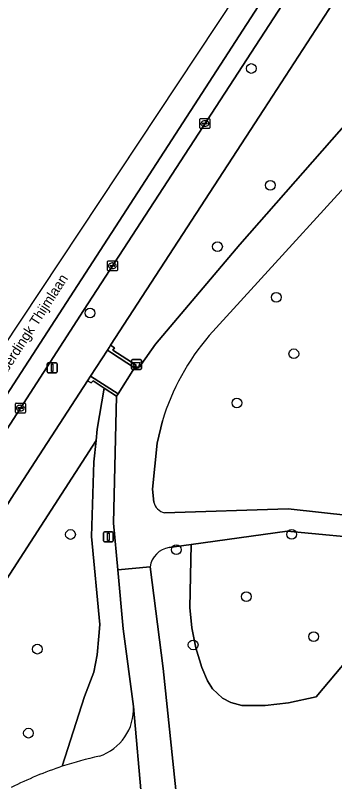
# Model space of a CAD drawing. Extents: x 161402 to 161933, y 381647 to 382315.
# Drawn here: x 161500.4 to 161532.4, y 381932.5 to 382009.5 of the extents above; entities that cross this region are included whole.
import ezdxf

# ---------------------------------------------------------------- set-up
doc = ezdxf.new("R2010")
doc.units = 0
for name, color, linetype in [('IMGEO_Afvalbak', 7, 'Continuous'), ('IMGEO_Boom', 7, 'Continuous'), ('IMGEO_Groenvoorziening', 7, 'Continuous'), ('IMGEO_Kolk', 7, 'Continuous'), ('IMGEO_Lichtmast', 7, 'Continuous'), ('IMGEO_Muur', 7, 'Continuous'), ('IMGEO_Openbare_ruimte_label', 7, 'Continuous'), ('IMGEO_Rijbaan_lokaal_gesloten', 7, 'Continuous'), ('IMGEO_Rijbaan_lokaal_open', 7, 'Continuous'), ('IMGEO_Voetpad_gesloten', 7, 'Continuous'), ('IMGEO_Voetpad_op_trap', 7, 'Continuous'), ('IMGEO_Voetpad_open', 7, 'Continuous')]:
    doc.layers.add(name, color=color, linetype=linetype)

msp = doc.modelspace()

# ---------------------------------------------------------------- linework, layer by layer
at = {"layer": 'IMGEO_Afvalbak'}
for p, q in [((161512.056, 381973.98), (161512.056, 381974.78)), ((161512.056, 381974.78), (161512.056, 381973.98)), ((161512.156, 381974.88), (161512.946, 381974.88)), ((161512.946, 381974.88), (161512.156, 381974.88)), ((161513.046, 381974.78), (161513.046, 381973.98)), ((161513.046, 381973.98), (161513.046, 381974.78)), ((161512.946, 381973.88), (161512.156, 381973.88)), ((161512.156, 381973.88), (161512.946, 381973.88))]:
    msp.add_line(p, q, dxfattribs=at)
msp.add_lwpolyline([(161512.199, 381974.594), (161512.903, 381974.594), (161512.754, 381974.124), (161512.348, 381974.124), (161512.199, 381974.594)], dxfattribs=at)
for centre, start, end in [((161512.156, 381974.78), 90, 180), ((161512.156, 381974.78), 90, 180), ((161512.946, 381974.78), 0, 90), ((161512.946, 381974.78), 360, 90), ((161512.156, 381973.98), 180, 270), ((161512.156, 381973.98), 180, 270), ((161512.946, 381973.98), 270, 0), ((161512.946, 381973.98), 270, 0)]:
    msp.add_arc(centre, 0.1, start, end, dxfattribs=at)
at = {"layer": 'IMGEO_Boom'}
for centre in [(161524.069, 382004.122), (161525.982, 381992.389), (161520.681, 381986.224), (161526.576, 381981.129), (161507.896, 381979.545), (161528.346, 381975.453), (161522.628, 381970.508), (161505.933, 381957.295), (161528.12, 381957.302), (161516.555, 381955.763), (161523.568, 381951.047), (161530.341, 381947.03), (161502.618, 381945.772), (161518.24, 381946.2), (161501.719, 381937.331)]:
    msp.add_circle(centre, 0.489, dxfattribs=at)
at = {"layer": 'IMGEO_Groenvoorziening'}
for points in [[(161550.139, 382016.903), (161566.397, 382035.429), (161561.912, 382038.8), (161560.125, 382041.115), (161560.053, 382046.091), (161561.918, 382049.386), (161564.736, 382052.445), (161569.199, 382053.861), (161571.62, 382051.637), (161574.693, 382046.208), (161579.356, 382052.267), (161579.545, 382052.829), (161579.122, 382053.921), (161568.086, 382063.783), (161567.337, 382064.038), (161566.628, 382063.688), (161525.324, 382000), (161509.956, 381976.304), (161510.352, 381976.047), (161510.195, 381975.805), (161512.522, 381974.297), (161512.354, 381974.043)], [(161513.027, 381974.379), (161514.478, 381976.419), (161522.917, 381986.45), (161534.836, 382000), (161550.139, 382016.903)], [(161544.568, 381990.984), (161544.697, 381994.341), (161539.026, 381998.34), (161519.862, 381977.295)], [(161515.352, 381959.463), (161527.77, 381959.887), (161537.2, 381958.819), (161538.012, 381964.131), (161537.399, 381965.184), (161541.408, 381970.096), (161542.413, 381969.37), (161547.271, 381970.949), (161546.429, 381973.583)], [(161510.676, 381953.741), (161510.253, 381958.443), (161510.563, 381971.196), (161509.308, 381972.015), (161508.618, 381967.87), (161508.501, 381966.732), (161508.281, 381964.587), (161508.029, 381957.094), (161508.87, 381948.254), (161508.777, 381947.074), (161508.622, 381945.207), (161508.281, 381943.455), (161507.356, 381941.013), (161505.105, 381933.996)], [(161515.15, 381968.709), (161514.646, 381966.471), (161514.174, 381961.84), (161514.294, 381960.547)], [(161505.105, 381933.996), (161507.356, 381941.013), (161508.281, 381943.455), (161508.622, 381945.207), (161508.777, 381947.074), (161508.87, 381948.254), (161508.029, 381957.094), (161508.281, 381964.587), (161508.501, 381966.732), (161469.767, 381906.69), (161463.799, 381897.019), (161472.803, 381891.338), (161466.75, 381881.87), (161480.283, 381895.461)], [(161533.668, 381906.095), (161532.917, 381915.131), (161532.824, 381921.008), (161533.225, 381929.262), (161534.202, 381939.899), (161534.991, 381946.237), (161530.572, 381940.988), (161527.811, 381940.367), (161525.479, 381940.12), (161523.133, 381940.118), (161522.019, 381940.405), (161521.193, 381940.842), (161520.168, 381941.793), (161519.671, 381942.584), (161519.118, 381943.929), (161518.506, 381945.898), (161518.104, 381947.92), (161517.916, 381949.973), (161518.029, 381956.285), (161515.84, 381955.982)], [(161512.254, 381940.023), (161511.211, 381947.806), (161510.676, 381953.741)], [(161513.937, 381954.035), (161515.234, 381943.813), (161516.591, 381930.663)]]:
    msp.add_lwpolyline(points, dxfattribs=at)
for points in [[(161463.799, 381897.019), (161469.767, 381906.69), (161508.501, 381966.732), (161508.618, 381967.87), (161509.308, 381972.015), (161508.198, 381972.739), (161508.017, 381972.531), (161507.649, 381972.745), (161500, 381960.897), (161499.565, 381960.223), (161466.384, 381908.825), (161460.416, 381899.153)], [(161535.316, 381948.041), (161535.492, 381949.019), (161536.744, 381955.964), (161536.884, 381956.742), (161527.675, 381957.619), (161518.029, 381956.285), (161517.916, 381949.973), (161518.104, 381947.92), (161518.506, 381945.898), (161519.118, 381943.929), (161519.671, 381942.584), (161520.168, 381941.793), (161521.193, 381940.842), (161522.019, 381940.405), (161523.133, 381940.118), (161525.479, 381940.12), (161527.811, 381940.367), (161530.572, 381940.988), (161534.991, 381946.237)]]:
    msp.add_lwpolyline(points, close=True, dxfattribs=at)
for centre, radius, start, end in [((161538.145, 381961.675), 24.046, 139.49162, 162.99238), ((161512.522, 381974.549), 0.533, 251.63031, 341.43166), ((161515.722, 381960.882), 1.466, 193.20622, 255.40291), ((161516.156, 381953.77), 2.235, 98.12568, 173.18388), ((161507.248, 381939.774), 5.012, 288.4124, 2.8499), ((161516.698, 381899.034), 36.834, 102.33201, 108.34471), ((161516.832, 381898.676), 37.216, 108.36728, 116.88998)]:
    msp.add_arc(centre, radius, start, end, dxfattribs=at)
at = {"layer": 'IMGEO_Kolk'}
for p, q in [((161518.916, 381998.165), (161518.916, 381999.017)), ((161518.991, 381999.091), (161519.843, 381999.091)), ((161519.175, 381998.585), (161519.175, 381998.597)), ((161519.613, 381998.548), (161519.215, 381998.548)), ((161519.218, 381998.634), (161519.616, 381998.634)), ((161519.404, 381998.871), (161519.429, 381998.871)), ((161519.659, 381998.597), (161519.659, 381998.585)), ((161519.917, 381999.017), (161519.917, 381998.165)), ((161519.843, 381998.091), (161518.991, 381998.091)), ((161519.427, 381998.311), (161519.402, 381998.311)), ((161509.644, 381983.873), (161509.644, 381984.725)), ((161509.719, 381984.799), (161510.571, 381984.799)), ((161510.132, 381984.579), (161510.157, 381984.579)), ((161510.645, 381984.725), (161510.645, 381983.873)), ((161510.571, 381983.799), (161509.719, 381983.799)), ((161509.903, 381984.293), (161509.903, 381984.305)), ((161510.341, 381984.256), (161509.943, 381984.256)), ((161509.946, 381984.342), (161510.344, 381984.342)), ((161510.155, 381984.019), (161510.13, 381984.019)), ((161510.387, 381984.305), (161510.387, 381984.293)), ((161500.415, 381969.577), (161500.415, 381970.429)), ((161500.49, 381970.503), (161501.342, 381970.503)), ((161500.674, 381969.997), (161500.674, 381970.009)), ((161501.112, 381969.96), (161500.714, 381969.96)), ((161500.717, 381970.046), (161501.115, 381970.046)), ((161500.903, 381970.283), (161500.928, 381970.283)), ((161501.158, 381970.009), (161501.158, 381969.997)), ((161501.416, 381970.429), (161501.416, 381969.577)), ((161501.342, 381969.503), (161500.49, 381969.503)), ((161500.926, 381969.723), (161500.901, 381969.723))]:
    msp.add_line(p, q, dxfattribs=at)
for points in [[(161518.916, 381998.165), (161518.916, 381999.017)], [(161518.991, 381999.091), (161519.843, 381999.091)], [(161519.917, 381999.017), (161519.917, 381998.165)], [(161519.843, 381998.091), (161518.991, 381998.091)], [(161509.644, 381983.873), (161509.644, 381984.725)], [(161509.719, 381984.799), (161510.571, 381984.799)], [(161510.645, 381984.725), (161510.645, 381983.873)], [(161510.571, 381983.799), (161509.719, 381983.799)], [(161500.415, 381969.577), (161500.415, 381970.429)], [(161500.49, 381970.503), (161501.342, 381970.503)], [(161501.416, 381970.429), (161501.416, 381969.577)], [(161501.342, 381969.503), (161500.49, 381969.503)]]:
    msp.add_lwpolyline(points, dxfattribs=at)
for centre, radius, start, end in [((161518.993, 381999.015), 0.0765, 91.55205, 178.44795), ((161518.993, 381999.015), 0.0765, 91.55205, 178.44795), ((161519.215, 381998.594), 0.0403, 85.87752, 175.75265), ((161519.212, 381998.584), 0.0366, 178.93798, 274.71019), ((161519.616, 381998.591), 0.043, 264.86636, 352.45326), ((161519.62, 381998.596), 0.0386, 1.73085, 96.63898), ((161519.841, 381999.015), 0.0765, 1.55205, 88.44795), ((161519.841, 381999.015), 0.0765, 1.55205, 88.44795), ((161518.993, 381998.167), 0.0765, 181.55205, 268.44795), ((161518.993, 381998.167), 0.0765, 181.55205, 268.44795), ((161519.841, 381998.167), 0.0765, 271.55205, 358.44795), ((161519.841, 381998.167), 0.0765, 271.55205, 358.44795), ((161509.721, 381984.723), 0.0765, 91.55205, 178.44795), ((161509.721, 381984.723), 0.0765, 91.55205, 178.44795), ((161510.569, 381984.723), 0.0765, 1.55205, 88.44795), ((161510.569, 381984.723), 0.0765, 1.55205, 88.44795), ((161509.721, 381983.875), 0.0765, 181.55205, 268.44795), ((161509.721, 381983.875), 0.0765, 181.55205, 268.44795), ((161509.943, 381984.302), 0.0403, 85.87752, 175.75265), ((161509.94, 381984.292), 0.0366, 178.93798, 274.71019), ((161510.344, 381984.299), 0.043, 264.86636, 352.45326), ((161510.348, 381984.304), 0.0386, 1.73085, 96.63898), ((161510.569, 381983.875), 0.0765, 271.55205, 358.44795), ((161510.569, 381983.875), 0.0765, 271.55205, 358.44795), ((161500.492, 381970.427), 0.0765, 91.55205, 178.44795), ((161500.492, 381970.427), 0.0765, 91.55205, 178.44795), ((161500.714, 381970.006), 0.0403, 85.87752, 175.75265), ((161500.711, 381969.996), 0.0366, 178.93798, 274.71019), ((161501.115, 381970.003), 0.043, 264.86636, 352.45326), ((161501.119, 381970.008), 0.0386, 1.73085, 96.63898), ((161501.34, 381970.427), 0.0765, 1.55205, 88.44795), ((161501.34, 381970.427), 0.0765, 1.55205, 88.44795), ((161500.492, 381969.579), 0.0765, 181.55205, 268.44795), ((161500.492, 381969.579), 0.0765, 181.55205, 268.44795), ((161501.34, 381969.579), 0.0765, 271.55205, 358.44795), ((161501.34, 381969.579), 0.0765, 271.55205, 358.44795)]:
    msp.add_arc(centre, radius, start, end, dxfattribs=at)
for centre, major_axis, ratio, start_param, end_param in [((161519.403, 381998.591), (-0.387, 0.002), 0.722429, 4.712389, 7.853982), ((161519.428, 381998.591), (-0.39, 0.002), 0.717154, 1.570796, 4.712389), ((161510.131, 381984.299), (-0.387, 0.002), 0.722429, 4.712389, 7.853982), ((161510.156, 381984.299), (-0.39, 0.002), 0.717154, 1.570796, 4.712389), ((161500.902, 381970.003), (-0.387, 0.002), 0.722429, 4.712389, 7.853982), ((161500.927, 381970.003), (-0.39, 0.002), 0.717154, 1.570796, 4.712389)]:
    msp.add_ellipse(centre, major_axis=major_axis, ratio=ratio, start_param=start_param, end_param=end_param, dxfattribs=at)
at = {"layer": 'IMGEO_Lichtmast'}
for p, q in [((161503.696, 381974.552), (161504.486, 381974.552)), ((161504.486, 381974.552), (161503.696, 381974.552)), ((161503.596, 381973.652), (161503.596, 381974.452)), ((161503.596, 381974.452), (161503.596, 381973.652)), ((161504.586, 381974.452), (161504.586, 381973.652)), ((161504.586, 381973.652), (161504.586, 381974.452)), ((161504.486, 381973.552), (161503.696, 381973.552)), ((161503.696, 381973.552), (161504.486, 381973.552)), ((161509.235, 381956.65), (161509.235, 381957.45)), ((161509.235, 381957.45), (161509.235, 381956.65)), ((161509.335, 381957.55), (161510.125, 381957.55)), ((161510.125, 381957.55), (161509.335, 381957.55)), ((161510.225, 381957.45), (161510.225, 381956.65)), ((161510.225, 381956.65), (161510.225, 381957.45)), ((161510.125, 381956.55), (161509.335, 381956.55)), ((161509.335, 381956.55), (161510.125, 381956.55))]:
    msp.add_line(p, q, dxfattribs=at)
for points in [[(161504.016, 381974.427), (161504.166, 381974.427), (161504.166, 381973.677), (161504.016, 381973.677), (161504.016, 381974.427)], [(161509.655, 381957.425), (161509.805, 381957.425), (161509.805, 381956.675), (161509.655, 381956.675), (161509.655, 381957.425)]]:
    msp.add_lwpolyline(points, dxfattribs=at)
for centre, start, end in [((161503.696, 381974.452), 90, 180), ((161503.696, 381974.452), 90, 180), ((161504.486, 381974.452), 0, 90), ((161504.486, 381974.452), 360, 90), ((161503.696, 381973.652), 180, 270), ((161503.696, 381973.652), 180, 270), ((161504.486, 381973.652), 270, 0), ((161504.486, 381973.652), 270, 0), ((161509.335, 381957.45), 90, 180), ((161509.335, 381957.45), 90, 180), ((161510.125, 381957.45), 0, 90), ((161510.125, 381957.45), 360, 90), ((161509.335, 381956.65), 180, 270), ((161509.335, 381956.65), 180, 270), ((161510.125, 381956.65), 270, 0), ((161510.125, 381956.65), 270, 0)]:
    msp.add_arc(centre, 0.1, start, end, dxfattribs=at)
at = {"layer": 'IMGEO_Muur'}
for points in [[(161510.195, 381975.805), (161510.352, 381976.047), (161509.956, 381976.304), (161509.806, 381976.073), (161509.648, 381975.83), (161510.055, 381975.566), (161512.354, 381974.043), (161512.522, 381974.297)], [(161507.953, 381973.214), (161507.649, 381972.745), (161508.017, 381972.531), (161508.198, 381972.739), (161509.308, 381972.015), (161510.563, 381971.196), (161510.709, 381971.428)]]:
    msp.add_lwpolyline(points, close=True, dxfattribs=at)
at = {"layer": 'IMGEO_Rijbaan_lokaal_gesloten'}
msp.add_lwpolyline([(161507.226, 381979.8), (161532.049, 382018.061), (161530.425, 382019.12), (161497.581, 381968.358), (161499.199, 381967.336)], close=True, dxfattribs=at)
at = {"layer": 'IMGEO_Rijbaan_lokaal_open'}
msp.add_lwpolyline([(161495.077, 381969.984), (161495.724, 381969.564), (161497.581, 381968.358), (161530.425, 382019.12), (161528.775, 382020.194), (161528.454, 382020.403)], close=True, dxfattribs=at)
at = {"layer": 'IMGEO_Voetpad_gesloten'}
for points in [[(161539.026, 381998.34), (161540.564, 382000), (161544.361, 382004.097), (161549.221, 382009.294), (161565.913, 382027.909), (161567.213, 382029.55), (161566.397, 382035.429), (161550.139, 382016.903), (161534.836, 382000), (161522.917, 381986.45), (161514.478, 381976.419), (161513.027, 381974.379)], [(161519.862, 381977.295), (161539.026, 381998.34)], [(161512.354, 381974.043), (161510.709, 381971.428), (161510.563, 381971.196), (161510.253, 381958.443), (161510.676, 381953.741), (161513.937, 381954.035)], [(161514.294, 381960.547), (161514.174, 381961.84), (161514.646, 381966.471), (161515.15, 381968.709)], [(161515.84, 381955.982), (161518.029, 381956.285), (161527.675, 381957.619), (161536.884, 381956.742), (161536.954, 381957.199), (161537.2, 381958.819), (161527.77, 381959.887), (161515.352, 381959.463)], [(161516.591, 381930.663), (161515.234, 381943.813), (161513.937, 381954.035), (161510.676, 381953.741), (161511.211, 381947.806), (161512.254, 381940.023), (161513.094, 381930.503)], [(161513.094, 381930.503), (161512.254, 381940.023)]]:
    msp.add_lwpolyline(points, dxfattribs=at)
for centre, radius, start, end in [((161538.145, 381961.675), 24.046, 139.49162, 162.99238), ((161512.522, 381974.549), 0.533, 251.63031, 341.43166), ((161515.722, 381960.882), 1.466, 193.20622, 255.40291), ((161516.156, 381953.77), 2.235, 98.12568, 173.18388), ((161507.248, 381939.774), 5.012, 288.4124, 2.8499), ((161516.698, 381899.034), 36.834, 102.33201, 108.34471), ((161516.832, 381898.676), 37.216, 108.36728, 116.88998)]:
    msp.add_arc(centre, radius, start, end, dxfattribs=at)
at = {"layer": 'IMGEO_Voetpad_op_trap'}
msp.add_lwpolyline([(161512.354, 381974.043), (161510.055, 381975.566), (161509.648, 381975.83), (161507.953, 381973.214), (161510.709, 381971.428)], close=True, dxfattribs=at)
at = {"layer": 'IMGEO_Voetpad_open'}
for points in [[(161525.324, 382000), (161566.628, 382063.688), (161570.174, 382069.09), (161571.745, 382071.279), (161574.421, 382075.333), (161608.435, 382119.953), (161605.683, 382121.518), (161591.922, 382103.449)], [(161578.467, 382089.284), (161576.388, 382086.507), (161541.352, 382032.43), (161540.784, 382031.553), (161532.638, 382018.971), (161532.049, 382018.061), (161507.226, 381979.8), (161499.199, 381967.336), (161498.606, 381966.417), (161490.128, 381953.282), (161489.562, 381952.406), (161448.908, 381889.474), (161447.556, 381887.381), (161443.733, 381881.365)], [(161442.026, 381870.534), (161448.68, 381880.995), (161454.261, 381889.705), (161454.272, 381889.698), (161460.416, 381899.153), (161466.384, 381908.825), (161499.565, 381960.223), (161500, 381960.897), (161507.649, 381972.745), (161507.953, 381973.214), (161509.648, 381975.83), (161509.806, 381976.073), (161509.956, 381976.304), (161525.324, 382000)]]:
    msp.add_lwpolyline(points, dxfattribs=at)

# ---------------------------------------------------------------- texts
at = {"layer": 'IMGEO_Openbare_ruimte_label'}
msp.add_text('Alberdingk Thijmlaan', height=1, rotation=57.24756, dxfattribs=at).set_placement((161498.973, 381972.542))

doc.saveas('drawing.dxf')
